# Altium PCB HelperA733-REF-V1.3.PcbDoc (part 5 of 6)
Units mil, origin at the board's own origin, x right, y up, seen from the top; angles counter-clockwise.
Board outline 5905.51 x 4133.86 mil, 2 copper layers (Top, Bottom), stack 12.7 mil thick; 446 components, 341 nets, 1706 pads, 1667 vias.
Unrouted connection lines stored in the file: 1382.
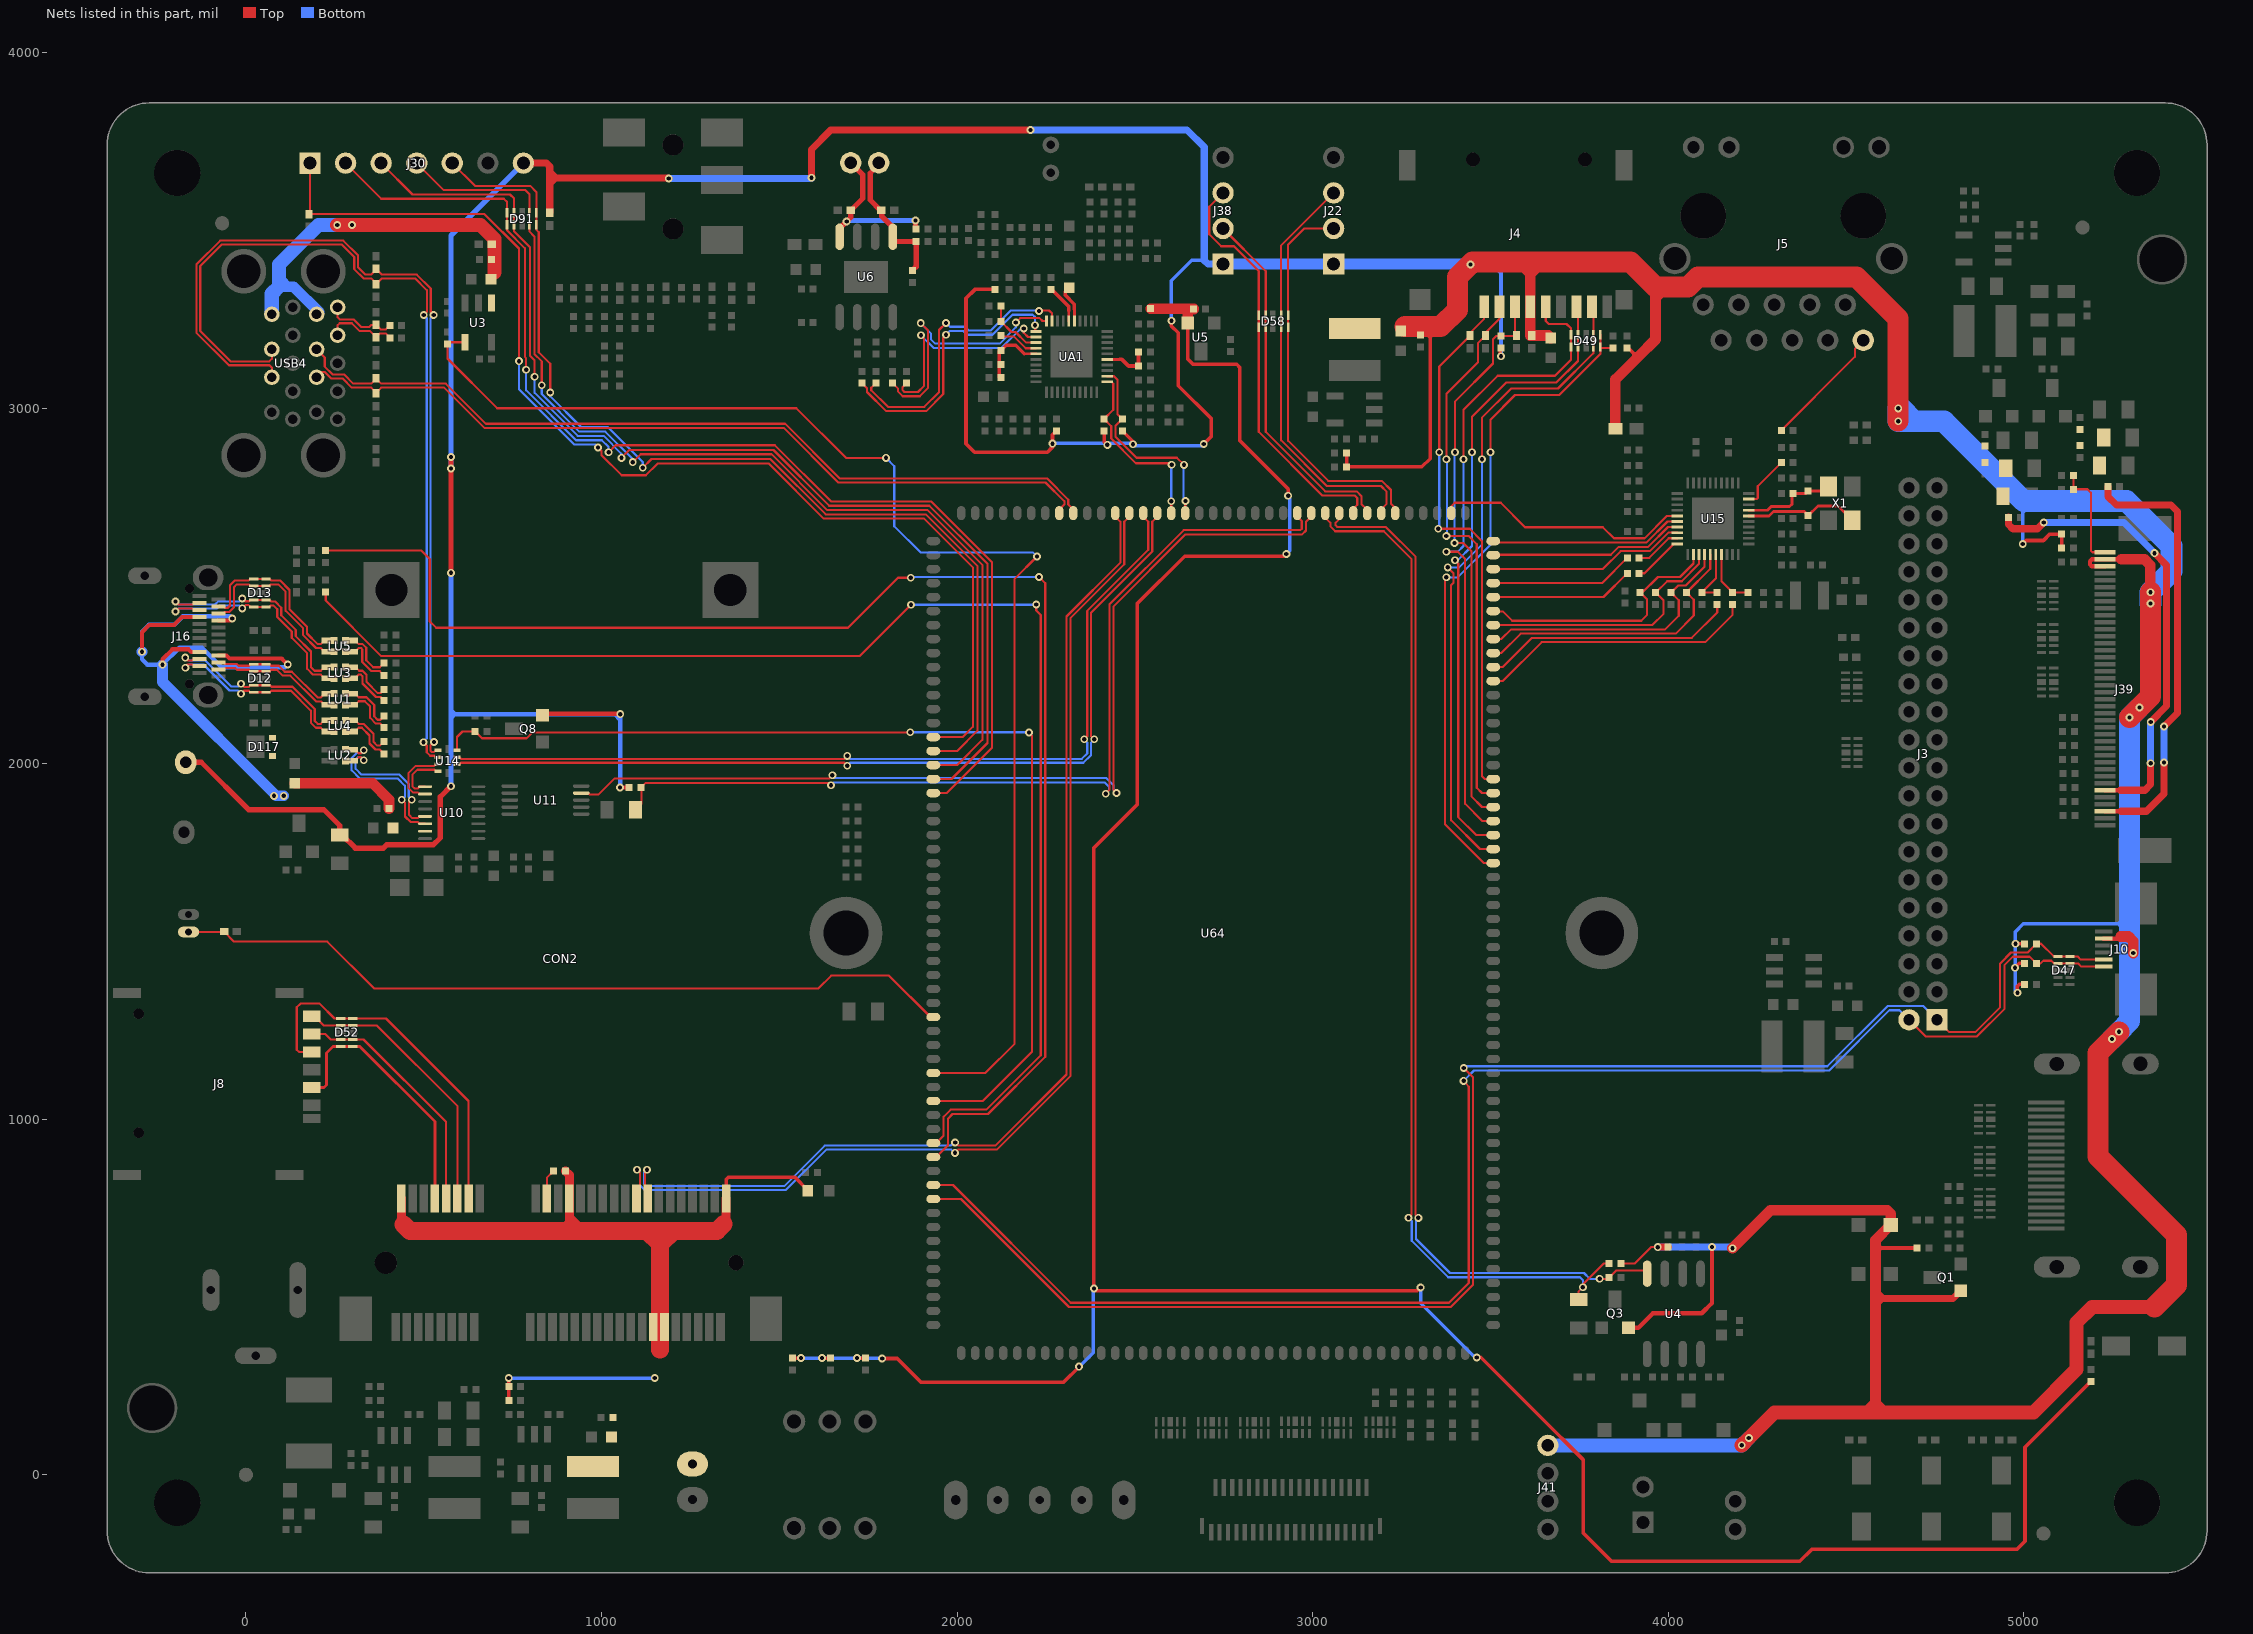
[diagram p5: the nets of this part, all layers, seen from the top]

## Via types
v1: diameter 22, hole 12, Top to Bottom, 1667 vias

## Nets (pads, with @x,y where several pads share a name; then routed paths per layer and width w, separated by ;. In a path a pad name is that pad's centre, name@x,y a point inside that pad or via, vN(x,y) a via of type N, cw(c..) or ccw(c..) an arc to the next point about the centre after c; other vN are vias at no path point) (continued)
RGMII0-RXCK: RE9.1 U64.84 | length 779.7
  Top w6: U64.84@3507.87,2232.28 3534.83,2232.28 3644.31,2341.76 4104.32,2341.76 4181.1,2418.54 RE9.1@4181.1,2447.84
RGMII0-RXCTL: RE14.1 U64.85 | length 716.3
  Top w6: U64.85@3507.87,2271.65 3534.92,2271.65 3617.03,2353.76 4066.53,2353.76 4137.8,2425.03 RE14.1@4137.8,2447.84
RGMII0-RXD0: RE40.1 U15.25 U64.86 | length 815.7
  Top w6: U64.86@3507.87,2311.02 3530.39,2311.02 3585.13,2365.76 4020.9,2365.76 4071.64,2416.5 4071.64,2460.84 RE40.1@4051.18,2481.3 4118.11,2548.23 U15.25@4118.11,2588.58
RGMII0-RXD1: RE38.1 U15.24 U64.87 | length 782.1
  Top w6: U64.87@3507.87,2350.39 3530.85,2350.39 3558.22,2377.76 3991.37,2377.76 4029.47,2415.86 4029.47,2459.7 RE38.1@4007.87,2481.3 4027.71,2501.13 4049.16,2501.13 4102.36,2554.34 U15.24@4102.36,2588.58
RGMII0-RXD2: RE36.1 U15.23 U64.88 | length 743.1
  Top w6: U64.88@3507.87,2389.76 3954.88,2389.76 3986.9,2421.79 3986.9,2458.97 RE36.1@3964.57,2481.3 3996.92,2513.13 4038.02,2513.13 4086.61,2561.73 U15.23@4086.61,2588.58
RGMII0-RXD3: RE25.1 U15.22 U64.89 | length 731
  Top w6: U64.89@3507.87,2429.13 3509.51,2427.5 3535.63,2427.5 3561.36,2401.77 3923.94,2401.77 3940.76,2418.59 3940.76,2461.8 RE25.1@3921.26,2481.3 3927.3,2481.3 3971.14,2525.14 4033.06,2525.14 4070.87,2562.95 U15.22@4070.87,2588.58
RGMII0-TXCK: RE7.1 U64.90 | length 404.7
  Top w6: U64.90@3507.87,2468.5 3817.91,2468.5 RE7.1@3884.84,2535.43
RGMII0-TXCTL: RE5.1 U64.91 | length 406.3
  Top w6: U64.91@3507.87,2507.87 3813.97,2507.87 RE5.1@3884.84,2578.74
RGMII0-TXD0: U15.18 U64.92 | length 560.1
  Top w6: U64.92@3507.87,2547.24 3815.85,2547.24 3866.21,2597.6 3948.39,2597.6 4000.39,2649.61 U15.18@4025.59,2649.61
RGMII0-TXD1: U15.17 U64.93 | length 550.3
  Top w6: U64.93@3507.87,2586.61 3508.69,2587.43 3838.65,2587.43 3860.89,2609.67 3943.49,2609.67 3999.17,2665.35 U15.17@4025.59,2665.35
RGMII0-TXD2: U15.16 U64.94 | length 544.1
  Top w6: U64.94@3507.87,2625.99 3512.18,2621.67 3938.51,2621.67 3997.95,2681.1 U15.16@4025.59,2681.1
RGMII0-TXD3: U15.15 U64.96 | length 726.3
  Top w6: U64.96@3389.76,2704.73 3389.76,2723.61 3399.75,2733.6 3528.8,2733.6 3597.37,2665.02 3816.12,2665.02 3847.33,2633.82 3933.69,2633.82 3996.72,2696.85 U15.15@4025.59,2696.85
RSET: RE22.2 U15.39 | length 153.1
  Top w6: U15.39@4226.38,2744.09 4248.32,2744.09 4251.79,2747.56 4251.79,2780.33 RE22.2@4317.91,2846.46
RTC-IN: D174.2 J14.2 U64.166 | length 2224.6
  Top w6: J14.2@-161.42,1526.57 -62.29,1526.57 D174.2@-61.31,1527.56 -61.31,1526.94 -33.75,1499.38 228.9,1499.38 360.31,1367.97 1610.22,1367.97 1646.25,1404 1808.6,1404 1925.19,1287.4 U64.166@1933.07,1287.4
RX-1N: D13.5 D13.6 J16.B10 LU3.4 RU119.1 | length 649.8
  Top w6: v1(-197.94,2427.93) -189.42,2436.44 -150.71,2436.44 -146.35,2432.09 J16.B10@-130.9,2432.09 ; v1(-10.42,2436.78) -1.3,2445.91 7.7,2445.91 12.66,2440.94 D13.5@22.33,2440.94 66.35,2440.94 70.69,2445.29 76.99,2445.29 88.21,2434.07 88.21,2412.23 128.96,2371.48 128.96,2354.14 172.2,2310.9 172.2,2266.66 188.46,2250.41 210.23,2250.41 220.47,2240.17 LU3.4@227.36,2240.17
  Bottom w6: v1(-197.94,2427.93) -189.44,2436.43 -82.42,2436.43 -73.57,2445.29 -18.92,2445.29 v1(-10.42,2436.78)
RX-1P: D13.4 D13.7 J16.B11 LU3.3 RU116.1 | length 648.8
  Top w6: v1(-197.94,2455.93) -189.46,2447.45 -149.89,2447.45 -145.58,2451.77 J16.B11@-130.9,2451.77 ; v1(-10.42,2464.78) -2.55,2456.92 8.84,2456.92 12.55,2460.62 D13.4@22.33,2460.62 66.14,2460.62 70.48,2456.28 81.62,2456.28 99.29,2438.62 99.29,2417.02 140.12,2376.18 140.12,2358.54 183.2,2315.46 183.2,2271.21 193.01,2261.41 210.23,2261.41 220.47,2271.65 LU3.3@227.36,2271.65
  Bottom w6: v1(-197.94,2455.93) -189.44,2447.43 -86.98,2447.43 -78.12,2456.28 -18.92,2456.28 v1(-10.42,2464.78)
RX-2N: D12.1 D12.10 J16.A10 LU1.3 RU109.1 | length 353.8
  Top w6: J16.A10@-77.76,2284.45 -62.41,2284.45 -58.07,2280.11 -25.77,2280.11 -20.85,2275.18 8.97,2275.18 13.32,2279.53 D12.1@22.33,2279.53 66.61,2279.53 70.96,2275.18 92.27,2275.18 108.93,2258.52 129.29,2258.52 201.55,2186.27 210.19,2186.27 220.77,2196.84 LU1.3@227.36,2196.84
RX-2P: D12.2 D12.9 J16.A11 LU1.4 RU108.1 | length 353.5
  Top w6: J16.A11@-77.76,2264.77 -62.98,2264.77 -58.64,2269.11 -30.33,2269.11 -25.4,2264.18 8.05,2264.18 12.4,2259.84 D12.2@22.33,2259.84 66.96,2259.84 71.3,2264.18 86.87,2264.18 103.56,2247.49 124.77,2247.49 197.11,2175.15 211.16,2175.15 220.94,2165.36 LU1.4@227.36,2165.36
RXC/PHYAD1: RE9.2 RE23.2 U15.27 | length 163.6
  Top w6: U15.27@4149.61,2588.58 4149.61,2512.8 RE9.2@4181.1,2481.3 RE23.2@4224.41,2481.3
RXCTL/PHYAD2: RE14.2 RE34.2 U15.26 | length 166.9
  Top w6: U15.26@4133.86,2588.58 4133.86,2520.67 RE34.2@4094.49,2481.3 4095.01,2481.3 RE14.2@4137.8,2481.3
S-TWI0-CTP0-SCK: D47.2 D47.9 J3.2 J10.6 R214.1 U64.178 | length 4335.5
  Top w6: U64.178@1933.07,814.96 1988.5,814.96 2319.55,483.91 3383.4,483.91 3438.91,539.42 3438.91,1091.93 v1(3424.58,1107.93) ; J3.2@4677.17,1279.53 4723.72,1232.97 4868.44,1232.97 4945.25,1309.78 4945.25,1433.21 4969.14,1457.09 5016.37,1457.09 R214.1@5035.21,1438.25 5047.28,1438.25 5054.92,1445.89 5077.44,1445.89 5085.08,1438.25 D47.2@5095.93,1438.25 5152.23,1438.25 5161.35,1429.13 J10.6@5224.41,1429.13
  Bottom w6: v1(3424.58,1107.93) 3453.84,1137.19 4452.59,1137.19 4621.86,1306.46 4650.23,1306.46 J3.2@4677.17,1279.53
S-TWI0-CTP0-SDA: D47.1 D47.10 J3.1 J10.5 R7.1 U64.179 | length 4385.8
  Top w6: U64.179@1933.07,775.59 2010.87,775.59 2314.56,471.9 3388.56,471.9 3450.91,534.25 3450.91,1117.94 v1(3424.92,1143.93) ; J3.1@4755.91,1279.53 4790.42,1245.01 4863.51,1245.01 4933.25,1314.75 4933.25,1438.18 4964.17,1469.09 5010.93,1469.09 R7.1@5035.21,1493.37 5048.44,1493.37 5083.87,1457.94 D47.1@5095.93,1457.94 5151.15,1457.94 5160.27,1448.82 J10.5@5224.41,1448.82
  Bottom w6: v1(3424.92,1143.93) 3430.18,1149.19 4447.6,1149.19 4616.94,1318.53 4650.48,1318.53 4716.91,1318.53 J3.1@4755.91,1279.53
SBU1-DC: RU23.1 U64.175 | length 3855.9
  Top w6: RU23.1@224.41,2483.27 224.41,2458.73 380.83,2302.31 1725.74,2302.31 v1(1870.37,2446.94) ; U64.175@1933.07,933.07 1940.94,933.07 1962.27,954.4 1962.27,1006.96 1982.23,1026.92 2082.35,1026.92 2235.31,1179.88 2235.31,2418.26 2222.81,2430.76 v1(2222.81,2447.32)
  Bottom w6: v1(1870.37,2446.94) 2222.81,2446.94 v1(2222.81,2447.32)
SBU2-DC: RU24.1 U64.176 | length 4090.2
  Top w6: RU24.1@224.41,2599.41 493.06,2599.41 516.91,2575.56 516.91,2400 534.8,2382.11 1693.35,2382.11 1833.97,2522.73 v1(1869.77,2522.73) ; U64.176@1933.07,893.7 1940.94,893.7 1974.27,927.03 1974.27,1001.83 1986.96,1014.52 2086.92,1014.52 2248.04,1175.64 2248.04,2507.46 v1(2230.62,2524.88)
  Bottom w6: v1(1869.77,2522.73) 1871.91,2524.88 v1(2230.62,2524.88)
SDC0-CLK: D49.1 D49.10 J4.5 U64.74 | length 1855.6
  Top w6: v1(3376,2596) 3408.29,2596 3428.9,2575.39 3428.9,1886.95 3477.27,1838.58 U64.74@3507.87,1838.58 ; v1(3424,2856) 3424,2994.85 3520.16,3091.01 3681.56,3091.01 3726.38,3135.83 3726.38,3224.07 3713.9,3236.55 3663.84,3236.55 3655.41,3244.98 3655.41,3285.43 J4.5@3655.51,3285.43
  Bottom w6: v1(3376,2596) 3408,2596 3424,2612 v1(3424,2856)
SDC0-CMD: D126.2 J4.3 R11.2 U64.75 | length 1606.6
  Top w6: v1(3399.14,2620.47) 3423.96,2620.47 3446.46,2597.98 3446.46,1907.87 3476.38,1877.95 U64.75@3507.87,1877.95 ; v1(3400,2876) 3400,3018.09 3507.24,3125.33 3507.24,3193.61 3516.45,3202.82 R11.2@3529.64,3202.82 D126.2@3568.9,3202.82 ; J4.3@3568.9,3285.43 D126.2@3568.9,3202.82 ; D126.2@3568.9,3202.82 3568.9,3197.13 D126.2@3572.95,3204.09 3571.68,3202.82 D126.2@3568.9,3202.82
  Bottom w6: v1(3399.14,2620.47) 3399.14,2876.86 v1(3400,2876)
SDC0-D0: D49.2 D49.9 J4.7 U64.73 | length 1791.5
  Top w6: v1(3400,2572) 3409.48,2562.52 3409.48,1849.73 3460,1799.21 U64.73@3507.87,1799.21 ; v1(3448,2876) 3448,2976 3544,3072 3685.46,3072 3746.06,3132.6 D49.2@3746.06,3171.85 D49.9@3746.06,3206.3 3746.06,3268.03 3742.13,3271.97 J4.7@3742.13,3285.43
  Bottom w6: v1(3400,2572) 3408,2572 3448,2612 v1(3448,2876)
SDC0-D1: D49.4 D49.7 J4.8 U64.72 | length 1873
  Top w6: v1(3380,2552) 3396.06,2535.94 3396.06,2509.08 3389.54,2502.56 3389.54,1840.78 3470.47,1759.84 U64.72@3507.87,1759.84 ; v1(3476,2856) 3476,2972.63 3558.37,3054.99 3690.1,3054.99 3789.37,3154.26 D49.4@3789.37,3171.85 D49.7@3789.37,3206.3 3789.37,3258.79 3785.43,3262.72 J4.8@3785.43,3285.43
  Bottom w6: v1(3380,2552) 3412,2552 3476,2616 v1(3476,2856)
SDC0-D2: D128.2 J4.1 U64.77 | length 1516.6
  Top w6: v1(3353.2,2660.88) v1@3352.4,2660.6 ; v1(3356,2876) 3356,3117.06 D128.2@3443.03,3204.09 3443.03,3211.68 3482.28,3250.94 J4.1@3482.28,3285.43 ; U64.77@3507.87,1956.69 3484.25,1956.69 3476.38,1964.57 3476.38,2625.88 3441.65,2660.6 v1@3352.4,2660.6 ; v1@3352.4,2660.6 3351.67,2660.6 3351.75,2660.38 v1@3352.4,2660.6
  Bottom w6: v1(3353.2,2660.88) 3356,2660.88 v1(3356,2876)
SDC0-D3: D127.2 J4.2 U64.76 | length 1544.1
  Top w6: v1(3376,2640) 3377.89,2640.59 3438.09,2640.59 3461.41,2617.26 3461.41,1932.29 3476.38,1917.32 U64.76@3507.87,1917.32 ; v1(3376,2856) 3376.42,2856.53 3376.42,3040.04 3464.57,3128.19 3464.57,3182.32 D127.2@3486.34,3204.09 3484.25,3209.6 3525.59,3250.94 J4.2@3525.59,3285.43
  Bottom w6: v1(3376,2640) 3377.57,2640.6 3377.57,2855.38 3376.47,2856.47 v1(3376,2856)
SDC0-DET: D49.5 D49.6 R294.1 U64.71 | length 1867.1
  Top w6: v1(3376,2524) 3372.21,2520.21 3372.21,1829.33 3481.06,1720.47 U64.71@3507.87,1720.47 ; v1(3500,2876) 3500,2967.62 3569.13,3036.75 3693.86,3036.75 3809.06,3151.94 D49.5@3809.06,3171.85 ; D49.6@3809.06,3206.3 D49.5@3809.06,3171.85 ; R294.1@3844.6,3169.36 3811.55,3169.36 D49.5@3809.06,3171.85
  Bottom w6: v1(3376,2524) 3408,2524 3500,2616 v1(3500,2876)
SPI0-CLK: D91.1 D91.10 J30.2 U64.150 | length 3326.1
  Top w6: J30.2@280.31,3688.98 380.43,3588.86 725.39,3588.86 734.07,3580.18 D91.10@734.07,3549.44 D91.1@734.07,3514.99 734.07,3499.76 784.36,3449.47 784.36,3144.19 788,3140.55 v1(788,3108) ; v1(1020,2876) 1039.54,2895.54 1487.45,2895.54 1645.42,2737.57 1926.73,2737.57 2098.21,2566.09 2098.21,2044.81 1970.72,1917.32 U64.150@1933.07,1917.32
  Bottom w6: v1(788,3108) 788,3049.77 928.23,2909.55 1001.12,2909.55 1020,2890.67 v1(1020,2876)
SPI0-CS0: D91.5 D91.6 J30.5 U64.147 | length 2900.9
  Top w6: J30.5@580.31,3688.98 644.43,3624.86 799.56,3624.86 816.75,3607.67 D91.6@816.75,3549.44 D91.5@816.75,3514.99 816.75,3501.13 823.51,3494.37 823.51,3157.07 856,3124.58 v1(856,3044) ; v1(1116,2832) 1140.59,2856.59 1474.71,2856.59 1630.26,2701.04 1912.29,2701.04 2057,2556.33 2057,2092.44 2000,2035.43 U64.147@1933.07,2035.43
  Bottom w6: v1(856,3044) 856,3032.99 942.37,2946.62 1017.85,2946.62 1116,2848.47 v1(1116,2832)
SPI0-CS1: D88.1 J30.1 U64.146 | length 3261.4
  Top w6: J30.1@180.31,3688.98 180.31,3548.71 D88.1@177.17,3545.56 671.09,3545.56 768,3448.65 v1(768,3132) ; v1(989.95,2889.46) 1000,2879.41 1000,2867.72 1056.69,2811.02 1124.48,2811.02 1157.71,2844.25 1470.05,2844.25 1625.32,2688.98 1907.38,2688.98 2044.28,2552.07 2044.28,2103.34 2015.75,2074.8 U64.146@1933.07,2074.8
  Bottom w6: v1(768,3132) 768,3052.8 923.27,2897.54 981.87,2897.54 v1(989.95,2889.46)
SPI0-MISO: D91.4 D91.7 J30.4 U64.148 | length 3050.7
  Top w6: J30.4@480.31,3688.98 556.43,3612.86 786.36,3612.86 797.06,3602.16 D91.7@797.06,3549.44 D91.4@797.06,3514.99 797.06,3496.85 811.16,3482.75 811.16,3152.19 832,3131.35 v1(832,3064) ; v1(1088,2848) 1110.02,2870.02 1478.37,2870.02 1635.29,2713.1 1917.2,2713.1 2071.19,2559.11 2071.19,2067.26 2000,1996.06 U64.148@1933.07,1996.06
  Bottom w6: v1(832,3064) 832,3039.72 937.87,2933.85 1010.87,2933.85 1088,2856.72 v1(1088,2848)
SPI0-MOSI: D91.2 D91.9 J30.3 U64.149 | length 3181.8
  Top w6: J30.3@380.31,3688.98 468.43,3600.86 742.76,3600.86 753.75,3589.87 D91.9@753.75,3549.44 D91.2@753.75,3514.99 753.75,3497.09 798.73,3452.12 798.73,3146.94 812,3133.66 v1(812,3088) ; v1(1056,2860) 1078.02,2882.02 1483.67,2882.02 1640.35,2725.34 1921.93,2725.34 2085.54,2561.73 2085.54,2057.98 1984.25,1956.69 U64.149@1933.07,1956.69
  Bottom w6: v1(812,3088) 812,3042.75 932.99,2921.76 1005.89,2921.76 1056,2871.64 v1(1056,2860)
SPKR+: CA85.1 D118.2 J37.1 U6.8 | length 472.7
  Top w15: U6.8@1669.4,3481.79 U6.8@1669.4,3504.77 ; U6.8@1669.4,3506.79 U6.8@1669.4,3504.77 ; J37.1@1700.81,3689.85 1734.85,3655.82 1734.85,3590.07 D118.2@1701.02,3556.24 1701.02,3536.39 v1(1689.43,3524.79) U6.8@1669.4,3504.77 ; v1(1882.88,3527.6) 1882.88,3503.36 1884.84,3503.36 CA85.1@1884.84,3503.94
  Bottom w15: v1(1689.43,3524.79) 1692.24,3527.6 v1(1882.88,3527.6)
SPKR-: CA88.1 D20.2 J37.2 R181.2 U6.5 | length 413.5
  Top w15: J37.2@1779.55,3689.85 1782.37,3687.04 1755.85,3660.52 1755.85,3585.46 1785.07,3556.24 D20.2@1787.07,3556.24 1788.57,3556.24 1788.57,3538.73 1819.4,3507.89 U6.5@1819.4,3481.79 1819.4,3468.5 CA88.1@1884.84,3468.5 1884.84,3397.64 R181.2@1874.02,3386.81
SPOLN: R192.1 UA1.12 | length 617.1
  Top w6: R192.1@1858.27,3069.88 1846.19,3057.8 1846.19,3051.33 1852.1,3045.42 1890.16,3045.42 1906.61,3061.87 1906.61,3196.45 v1(1898.24,3204.82) ; v1(2187.48,3223.68) 2187.48,3211.99 2199.64,3199.83 UA1.12@2221.65,3199.83
  Bottom w6: v1(1898.24,3204.82) 1933.87,3169.19 2124.74,3169.19 2176.18,3220.63 2184.43,3220.63 v1(2187.48,3223.68)
SPOLP: R193.1 UA1.11 | length 789.9
  Top w6: R193.1@1732.28,3069.88 1746.72,3055.45 1746.72,3045.3 1800.71,2991.31 1912.89,2991.31 1961,3039.42 1961,3198.3 v1(1969,3206.3) ; v1(2218.93,3233.06) 2219.97,3233.02 2219.97,3215.58 UA1.11@2221.65,3215.58
  Bottom w6: v1(1969,3206.3) 1979.34,3216.64 2017.29,3216.64 2027.63,3206.3 2099.69,3206.3 2155.93,3262.54 2212.39,3262.54 2218.93,3256 v1(2218.93,3233.06) v1@2213.97,3233.02
SPORN: R194.1 UA1.10 | length 748.7
  Top w6: R194.1@1818.9,3069.88 1834.16,3054.62 1834.16,3046.28 1847.15,3033.29 1895,3033.29 1918.62,3056.91 1918.62,3217.98 v1(1897.66,3238.94) ; v1(2165.36,3240.85) 2177.57,3253.06 2232.25,3253.06 2240.21,3245.1 UA1.10@2251.18,3245.1
  Bottom w6: v1(1897.66,3238.94) 1926.42,3210.18 1926.42,3193.61 1938.84,3181.19 2119.69,3181.19 2165.36,3226.86 v1(2165.36,3240.85)
SPORP: R191.1 UA1.9 | length 811.1
  Top w6: R191.1@1771.65,3069.88 1758.77,3057 1758.77,3050.33 1805.79,3003.31 1907.65,3003.31 1948.99,3044.65 1948.99,3219.42 v1(1969.11,3239.54) ; v1(2230.13,3273.12) 2230.13,3274.56 2258.59,3274.56 2266.92,3266.23 UA1.9@2266.92,3245.1
  Bottom w6: v1(1969.11,3239.54) 1979.97,3228.68 2022.34,3228.68 2032.72,3218.3 2094.72,3218.3 2150.98,3274.56 2225.48,3274.56 v1(2230.13,3273.12)
TRM-CTR: C81.2 J5.1 | length 349.3
  Top w6: C81.2@4317.91,2937.01 4411.96,3031.05 4411.96,3031.46 4524.95,3144.45 4524.95,3167.06 J5.1@4548.61,3190.72
TWI8-SCK: RA27.1 U64.115 UA1.32 | length 572.3
  Top w6: UA1.32@2422.44,3089.59 2441.18,3089.59 2451.25,3079.53 2451.25,2982.81 RA27.1@2464.57,2969.49 2445.72,2950.64 2445.72,2919.33 2504.57,2860.48 2618.26,2860.48 v1(2638.4,2840.33) ; U64.115@2641.73,2704.73 2641.73,2738.37 v1(2642.21,2738.86)
  Bottom w6: v1(2638.4,2840.33) 2636.29,2840.33 2636.29,2744.78 v1(2642.21,2738.86)
TWI8-SDA: RA28.1 U64.116 UA1.31 | length 529.1
  Top w6: UA1.31@2422.44,3073.84 2434.25,3073.84 2439.21,3068.88 2439.21,2995.31 RA28.1@2413.39,2969.49 2433.72,2949.15 2433.72,2914.25 2502.95,2845.02 2598.9,2845.02 v1(2603.45,2840.47) ; v1(2602.31,2738.17) 2602.36,2738.11 U64.116@2602.36,2704.73
  Bottom w6: v1(2602.31,2738.17) 2602.31,2839.32 v1(2603.45,2840.47)
TX-1N: D13.2 D13.9 J16.A3 LU5.4 RU112.1 | length 497.2
  Top w6: J16.A3@-77.76,2422.24 -63.2,2422.24 -58.86,2426.58 -47.14,2426.58 -33.7,2440.02 -33.7,2496.52 -25.88,2504.34 7.41,2504.34 11.76,2500 D13.2@22.33,2500 65.66,2500 70,2504.34 91.15,2504.34 111.55,2483.94 111.55,2430.14 160.83,2380.86 160.83,2361.33 196.96,2325.21 210.23,2325.21 220.47,2314.97 LU5.4@227.36,2314.97
TX-1P: D13.1 D13.10 J16.A2 LU5.3 RU111.1 | length 497.3
  Top w6: J16.A2@-77.76,2441.93 -62.35,2441.93 -58,2437.58 -51.81,2437.58 -44.71,2444.68 -44.71,2501.31 -30.68,2515.34 7.73,2515.34 12.07,2519.68 D13.1@22.33,2519.68 66.61,2519.68 70.96,2515.34 95.71,2515.34 122.72,2488.33 122.72,2434.53 171.83,2385.42 171.83,2365.89 201.51,2336.21 210.23,2336.21 220.47,2346.45 LU5.3@227.36,2346.45
TX-2N: D12.4 D12.7 J16.B3 LU4.3 RU114.1 | length 555
  Top w6: v1(-170.8,2298.18) -162.85,2290.23 -162.85,2289.95 -151.02,2289.95 -146.68,2294.29 J16.B3@-130.9,2294.29 ; v1(-13.7,2224.77) -4.94,2216 7.81,2216 12.28,2220.47 D12.4@22.33,2220.47 67.5,2220.47 71.84,2216.13 131.17,2216.13 193.63,2153.67 193.63,2119.86 201.69,2111.8 210.23,2111.8 220.47,2122.04 LU4.3@227.36,2122.04
  Bottom w6: v1(-170.8,2298.18) -167.62,2298.18 -159.38,2289.95 -114.25,2289.95 -41.14,2216.84 -21.63,2216.84 v1(-13.7,2224.77)
TX-2P: D12.5 D12.6 J16.B2 LU4.4 RU113.1 | length 559.7
  Top w6: v1(-170.33,2269.88) -169.98,2270.65 -172.41,2271.75 -172.31,2271.86 -165.22,2278.95 -151.07,2278.95 -146.73,2274.61 J16.B2@-130.9,2274.61 ; v1(-13.7,2196.77) -5.47,2205 8.25,2205 12.46,2200.79 D12.5@22.33,2200.79 67.28,2200.79 71.62,2205.13 126.62,2205.13 182.63,2149.12 182.63,2114.91 196.74,2100.8 210.23,2100.8 220.47,2090.56 LU4.4@227.36,2090.56
  Bottom w6: v1(-170.33,2269.88) -168.3,2269.89 -159.25,2278.95 -119.22,2278.95 -46.09,2205.82 -22.76,2205.82 v1(-13.7,2196.77)
TXC: RE7.2 U15.20 | length 141.5
  Top w6: RE7.2@3918.31,2535.43 3933.39,2535.43 4016.07,2618.11 U15.20@4025.59,2618.11
TXCTL: RE5.2 U15.19 | length 130.1
  Top w6: RE5.2@3918.31,2578.74 3946.5,2578.74 4001.61,2633.86 U15.19@4025.59,2633.86
TYPEC-RX1N: LU3.1 R76.2 RU119.2 | length 154.9
  Top w6: RU119.2@280.51,2240.16 LU3.1@300.19,2240.17 ; LU3.1@300.19,2240.17 306.39,2240.17 316.63,2250.41 323.37,2250.41 327.91,2245.87 327.91,2225.38 365.87,2187.41 378.53,2187.41 R76.2@388.78,2177.17
TYPEC-RX1P: LU3.2 R77.2 RU116.2 | length 154.8
  Top w6: RU116.2@280.51,2271.65 LU3.2@300.19,2271.65 308.55,2271.65 318.79,2261.41 327.93,2261.41 338.98,2250.35 338.98,2229.93 370.49,2198.41 378.53,2198.41 R77.2@388.78,2208.66
TYPEC-RX2N: LU1.2 R65.2 RU109.2 | length 161.6
  Top w6: RU109.2@280.51,2196.85 LU1.2@300.19,2196.84 307.08,2196.84 317.32,2186.6 339.1,2186.6 360.74,2164.97 360.74,2132.97 370.1,2123.61 378.53,2123.61 R65.2@388.78,2133.86
TYPEC-RX2P: LU1.1 R69.2 RU108.2 | length 161.6
  Top w6: RU108.2@280.51,2165.35 LU1.1@300.19,2165.36 307.08,2165.36 317.32,2175.6 334.55,2175.6 349.43,2160.71 349.43,2128.65 365.47,2112.61 378.53,2112.61 R69.2@388.78,2102.36
TYPEC-TX1N: C139.2 LU5.1 RU112.2 | length 165.2
  Top w6: RU112.2@280.51,2314.96 LU5.1@300.19,2314.97 ; LU5.1@300.19,2314.97 307.08,2314.97 317.32,2325.21 323.48,2325.21 327.27,2321.42 327.27,2286.09 353.11,2260.25 376.56,2260.25 C139.2@388.78,2248.03
TYPEC-TX1P: C140.2 LU5.2 RU111.2 | length 165.2
  Top w6: RU111.2@280.51,2346.46 LU5.2@300.19,2346.45 307.08,2346.45 317.32,2336.21 328.08,2336.21 338.27,2326.02 338.27,2290.68 357.71,2271.25 376.56,2271.25 C140.2@388.78,2283.46
TYPEC-TX2N: C141.2 LU4.2 RU114.2 | length 156.1
  Top w6: RU114.2@280.51,2122.05 LU4.2@300.19,2122.04 307.08,2122.04 317.32,2111.8 330.77,2111.8 358.56,2084.02 358.56,2061.38 369.16,2050.78 376.56,2050.78 C141.2@388.78,2062.99
TYPEC-TX2P: C142.2 LU4.1 RU113.2 | length 156
  Top w6: RU113.2@280.51,2090.55 LU4.1@300.19,2090.56 307.08,2090.56 317.32,2100.8 325.95,2100.8 347.55,2079.2 347.55,2056.79 364.57,2039.78 376.56,2039.78 C142.2@388.78,2027.56
U3-TXN: C213.2 D74.1 USB4.17 | length 205.8
  Top w6: USB4.17@257.87,3204.72 257.87,3233.09 263.37,3238.59 297.83,3238.59 319.16,3217.26 348.4,3217.26 366.26,3199.4 D74.1@366.26,3199.26 377.21,3210.21 393.41,3210.21 405.63,3197.99 C213.2@404.65,3197.01
U3-TXP: C214.2 D75.1 USB4.18 | length 198.7
  Top w6: USB4.18@257.87,3283.46 257.87,3255.09 263.37,3249.59 302.38,3249.59 323.72,3228.26 347.39,3228.26 353.26,3234.13 D75.1@366.26,3234.13 379.16,3221.23 393.43,3221.23 C214.2@404.65,3232.44
UART0-RX: D173.1 R291.1 U64.107 | length 2645
  Top w6: D173.1@1095.12,1870.08 1112.48,1887.44 1112.48,1931.81 R291.1@1111.22,1933.07 1124.03,1945.88 1642.24,1945.88 1647.16,1940.96 v1(1645.46,1939.27) ; v1(2417.9,1915.6) 2428.13,1925.83 2428.13,2447.47 2637.49,2656.83 2965.45,2656.83 2969.4,2660.77 2969.4,2682.35 2956.69,2695.06 U64.107@2956.69,2704.73
  Bottom w6: v1(1645.46,1939.27) 1653.34,1947.15 2415.02,1947.15 2427.68,1934.49 2427.68,1925.38 v1(2417.9,1915.6)
UART0-TX: U11.9 U64.106 | length 2774.1
  Top w6: U11.9@942.91,1917.32 962.23,1917.32 966.02,1913.53 991.8,1913.53 1037.02,1958.74 1640.68,1958.74 v1(1649.29,1967.35) ; v1(2448.54,1917.48) 2440.13,1925.89 2440.13,2442.49 2642.46,2644.83 2970.42,2644.83 2981.4,2655.8 2981.4,2680.61 2996.06,2695.27 U64.106@2996.06,2704.73
  Bottom w6: v1(1649.29,1967.35) 1647.73,1965.79 1654.38,1959.15 2419.99,1959.15 2439.68,1939.46 2439.68,1926.34 v1(2448.54,1917.48)
UART2-RX: D54.1 R44.1 U64.105 | length 2926.8
  Top w6: U64.105@3035.43,2704.73 3035.43,2691.91 3049.73,2677.61 3049.73,2667.55 3063.65,2653.63 3199.9,2653.63 3277.46,2576.07 3277.46,731.12 v1(3269.26,722.92) ; D54.1@3748.03,492.76 3748.03,515.75 v1(3759.84,527.56) 3759.84,535.43 3818.9,594.49 R44.1@3833.66,594.49
  Bottom w6: v1(3269.26,722.92) 3278.68,713.49 3278.68,658.22 3381.34,555.56 3751.97,555.56 3759.84,547.69 v1(3759.84,527.56)
UART2-TX: R47.2 U4.4 U64.104 | length 2937.1
  Top w6: U64.104@3074.8,2704.73 3074.8,2687.6 3064.58,2677.38 3064.58,2670.04 3068.98,2665.64 3205.37,2665.64 3289.52,2581.49 3289.52,730.24 3297.17,722.59 v1(3297.27,722.59) ; v1(3807.09,551.18) 3833.66,551.18 R47.2@3833.66,555.12 3853.35,574.8 3931.7,574.8 U4.4@3940.75,565.76
  Bottom w6: v1(3297.27,722.59) 3290.72,716.05 3290.72,663.19 3386.34,567.57 3763.14,567.57 3779.53,551.18 v1(3807.09,551.18)
UART3-RX: D58.2 D58.9 J22.3 U64.101 | length 1179.9
  Top w6: J22.3@3059.06,3605.12 2911.42,3457.48 D58.2@2911.42,3261.22 D58.9@2911.42,3226.77 2911.42,2909.45 3039.98,2780.89 3192.07,2780.89 3208.14,2764.82 3208.14,2730.91 3192.91,2715.68 U64.101@3192.91,2704.73
UART3-TX: D58.1 D58.10 J22.2 U64.100 | length 1115.2
  Top w6: J22.2@3059.06,3505.12 2976.04,3505.12 2931.1,3460.18 D58.1@2931.1,3261.22 D58.10@2931.1,3226.77 2931.1,2907.95 3043.78,2795.28 3194.65,2795.28 3220.18,2769.74 3220.18,2731.02 3232.28,2718.93 U64.100@3232.28,2704.73
UART4-RX: D58.5 D58.6 J38.3 U64.103 | length 1168.1
  Top w6: J38.3@2748.03,3605.12 2709.03,3566.12 2709.03,3488.96 2742.88,3455.12 2778.62,3455.12 2848.42,3385.31 D58.5@2848.42,3261.22 D58.6@2848.42,3226.77 2848.42,2933.07 3027.83,2753.67 3118.89,2753.67 3125.56,2747 3125.56,2727.91 3114.17,2716.53 U64.103@3114.17,2704.73
UART4-TX: D58.4 D58.7 J38.2 U64.102 | length 1020.1
  Top w6: J38.2@2748.03,3505.12 2868.11,3385.04 D58.4@2868.11,3261.22 D58.7@2868.11,3226.77 2868.11,2933.07 3035.47,2765.71 3123.86,2765.71 3137.56,2752.01 3137.56,2729.83 3153.54,2713.85 U64.102@3153.54,2704.73
UPUSB-DM: LU2.3 RU22.1 U10.5 | length 427.1
  Top w6: RU22.1@280.51,2007.87 LU2.3@300.19,2007.88 307.08,2007.88 317.32,2018.12 322.9,2018.12 v1(331.4,2009.62) ; v1(466.4,1898.32) 465.37,1898.32 458.42,1891.37 458.42,1856.02 467.6,1846.84 483.2,1846.84 488.13,1851.77 U10.5@503.94,1851.77
  Bottom w6: v1(331.4,2009.62) 322.07,2018.96 315.87,2018.96 308.46,2011.55 308.46,1985.61 324.63,1969.44 431.06,1969.44 457.9,1942.6 457.9,1906.82 v1(466.4,1898.32)
UPUSB-DP: LU2.4 RU19.1 U10.6 | length 463.4
  Top w6: RU19.1@280.51,2039.37 LU2.4@300.19,2039.36 ; LU2.4@300.19,2039.36 307.08,2039.36 317.32,2029.12 322.9,2029.12 v1(331.4,2037.62) ; v1(438.4,1898.32) 439.43,1898.32 447.42,1890.34 447.42,1851.46 463.04,1835.84 483.12,1835.84 488.05,1830.91 U10.6@503.94,1830.91
  Bottom w6: v1(331.4,2037.62) 323.86,2030.08 311.42,2030.08 297.31,2015.97 297.31,1981.2 320.07,1958.44 426.5,1958.44 446.9,1938.04 446.9,1906.82 v1(438.4,1898.32)
USB0-DM: U14.7 U64.117 | length 2566
  Top w6: U14.7@593.51,1998.03 600.58,1998.03 604.92,2002.37 1682.57,2002.37 v1(1691.07,1993.87) ; v1(2385.51,2068.47) 2377.01,2076.97 2377.01,2167.42 2377.01,2424.96 2548.8,2596.75 2548.8,2680.69 2562.99,2694.88 U64.117@2562.99,2704.73
  Bottom w6: v1(1691.07,1993.87) 1699.57,2002.37 2355.19,2002.37 2377.01,2024.19 2377.01,2059.97 v1(2385.51,2068.47)
USB0-DM-L0-: D171.1 U14.2 USB4.2 | length 2550.9
  Top w6: USB4.2@72.83,3165.35 72.83,3138.38 65.93,3131.48 -43.25,3131.48 -128.37,3216.61 -128.37,3399.44 -67.83,3459.98 269.37,3459.98 304.61,3424.74 304.61,3390.74 330.61,3364.74 352.39,3364.74 366.26,3350.87 D171.1@366.26,3348.87 381.72,3364.33 476,3364.33 508.74,3331.59 508.74,3270.32 v1(499.91,3261.49) ; v1(499.38,2059.97) 508.41,2050.94 508.41,2031.81 518.15,2022.06 529.56,2022.06 533.9,2017.71 U14.2@540.35,2017.71
  Bottom w6: v1(499.38,2059.97) 498.94,2061.73 508.41,2071.2 508.41,3252.99 v1(499.91,3261.49)
USB0-DM-L1-: U10.1 U14.4 | length 152.4
  Top w6: U10.1@503.94,1935.24 488.19,1935.24 483.26,1930.3 474.53,1930.3 467.99,1936.84 467.99,1968.56 482.12,1982.69 529.72,1982.69 534.07,1978.34 U14.4@540.35,1978.34
USB0-DP: U14.8 U64.118 | length 2547.8
  Top w6: U14.8@593.51,2017.71 600.33,2017.71 604.67,2013.37 1682.57,2013.37 v1(1691.07,2021.87) ; v1(2357.51,2068.47) 2366.01,2076.97 2366.01,2171.97 2366.01,2429.62 2537.8,2601.41 2537.8,2680.69 2523.62,2694.88 U64.118@2523.62,2704.73
  Bottom w6: v1(1691.07,2021.87) 1699.57,2013.37 2350.64,2013.37 2366.01,2028.75 2366.01,2059.97 v1(2357.51,2068.47)
USB0-DP-L0+: D170.1 U14.1 USB4.3 | length 2587.7
  Top w6: USB4.3@72.83,3086.61 72.83,3114.14 66.49,3120.48 -47.8,3120.48 -139.37,3212.05 -139.37,3404 -72.39,3470.98 273.93,3470.98 315.61,3429.3 315.61,3395.29 335.17,3375.74 352.39,3375.74 366.26,3389.61 D170.1@366.26,3391.61 382.53,3375.34 480.85,3375.34 519.75,3336.44 519.75,3269.64 v1(527.91,3261.49) ; v1(528.6,2060.78) 519.41,2051.59 519.41,2036.41 522.75,2033.06 529.2,2033.06 533.55,2037.4 U14.1@540.35,2037.4
  Bottom w6: v1(527.91,3261.49) 519.41,3252.99 519.41,2069.97 v1(528.6,2060.78)
USB0-DP-L1+: U10.2 U14.3 | length 189.5
  Top w6: U10.2@503.94,1914.37 488.19,1914.37 483.26,1919.3 469.35,1919.3 456.71,1931.94 456.71,1972.95 477.45,1993.69 529.37,1993.69 533.72,1998.03 U14.3@540.35,1998.03
USB0-SL-PL2: RU6.2 U14.9 U64.172 | length 2904.1
  Top w6: U14.9@593.51,2037.4 593.51,2075.14 608.92,2090.55 RU6.2@644.69,2090.55 663.84,2071.4 789.37,2071.4 805.9,2087.93 1868.41,2087.93 v1(1868.41,2088.53) ; U64.172@1933.07,1051.18 2072.39,1051.18 2210.22,1189.01 2210.22,2079.09 v1(2202,2087.31)
  Bottom w6: v1(1868.41,2088.53) 1868.7,2088.25 2189.05,2088.25 v1(2202,2087.31)
USB1-DM: CON2.36 U64.119 | length 3143.3
  Top w6: CON2.36@1098.43,777.62 1098.43,804.43 1108,814 1108,850 v1(1100,858) ; v1(1993.81,905.48) 2002.95,914.62 2111.97,914.62 2318.62,1121.27 2318.62,2409.24 2470.06,2560.68 2470.06,2680.69 2484.25,2694.88 U64.119@2484.25,2704.73
  Bottom w6: v1(1100,858) 1108.5,849.5 1108.5,813.72 1121.41,800.81 1518.47,800.81 1632.28,914.62 1983.89,914.62 1993.03,905.48 v1(1993.81,905.48)
USB1-DP: CON2.38 U64.120 | length 3124.9
  Top w6: CON2.38@1129.92,777.62 1122,769.7 1122,852 v1(1128,858) v1@1130.38,856.82 ; v1@1129.92,855.92 v1@1130.37,856.79 ; v1(1994.52,934.81) 2003.71,925.62 2107.42,925.62 2307.62,1125.83 2307.62,2413.82 2459.06,2565.26 2459.06,2680.69 2444.88,2694.88 U64.120@2444.88,2704.73
  Bottom w6: v1(1128,858) 1119.5,849.5 1119.5,818.28 1125.97,811.81 1513.91,811.81 1627.72,925.62 1981.48,925.62 1990.67,934.81 v1(1994.52,934.81)
USB2-DM: D71.1 U64.123 USB4.11 | length 2361.2
  Top w6: USB4.11@198.81,3165.35 221.73,3142.43 221.73,3116.67 244.13,3094.27 276.46,3094.27 302.08,3068.65 352.39,3068.65 D71.1@366.26,3082.52 ; D71.1@366.26,3084.52 D71.1@366.26,3082.52 ; U64.123@2326.77,2704.73 2326.77,2714.56 2312.58,2728.75 2312.58,2742.6 2253.32,2801.86 1670.43,2801.86 1516.31,2955.98 674.65,2955.98 561.98,3068.65 380.13,3068.65 D71.1@366.26,3082.52
USB2-DP: D70.1 U64.124 USB4.12 | length 2312.1
  Top w6: USB4.12@198.81,3086.61 213.73,3101.53 221.31,3101.53 239.57,3083.27 271.9,3083.27 297.52,3057.65 352.39,3057.65 D70.1@366.26,3043.78 ; D70.1@366.26,3041.78 D70.1@366.26,3043.78 ; U64.124@2287.4,2704.73 2287.4,2714.56 2301.58,2728.75 2301.58,2737.89 2248.63,2790.84 1665.81,2790.84 1512.23,2944.42 670.56,2944.42 557.33,3057.65 380.13,3057.65 D70.1@366.26,3043.78
USIM_CLK: CON2.12 D52.4 D52.7 J8.3 | length 773.7
  Top w6: J8.3@185.04,1289.37 193.5,1289.37 219.09,1263.78 D52.7@266.42,1263.78 368.36,1263.78 594.49,1037.66 CON2.12@594.49,777.62
USIM_DATA: CON2.10 D52.2 D52.9 J8.7 | length 694.9
  Top w6: J8.7@185.04,1239.37 223.82,1239.37 238.77,1224.41 D52.9@266.42,1224.41 330.7,1224.41 562.99,992.12 CON2.10@562.99,777.62
USIM_RST: CON2.14 D52.5 D52.6 J8.2 | length 1038.2
  Top w6: J8.2@185.04,1189.37 149.18,1189.37 143,1195.55 143,1314.82 153.41,1325.23 207.33,1325.23 249.1,1283.46 D52.6@266.42,1283.46 393.7,1283.46 625.99,1051.18 CON2.14@625.99,777.62
USIM_VCC: CON2.8 D52.1 D52.10 J8.1 | length 750.3
  Top w8: J8.1@185.04,1089.37 219.45,1089.37 226.21,1096.13 226.21,1186.1 244.83,1204.72 D52.10@266.42,1204.72 320.2,1204.72 531.5,993.42 CON2.8@531.5,777.62
VBUS1: CU2.2 CU3.2 D67.2 U3.1 USB4.1 USB4.10 | length 1133.8
  Top w40: v1(256.83,3515.2) v1(298.51,3515.2) 659.42,3515.2 699.39,3475.24 699.39,3382.23
  Bottom w30: 93.02,3341.66 116.27,3341.66 ; 93.02,3359.25 98.68,3359.25 116.27,3341.66 ; USB4.10@198.81,3263.77 205.35,3270.31 134.01,3341.66 116.27,3341.66
  Bottom w40: USB4.1@72.83,3263.77 72.83,3321.48 93.02,3341.66 93.02,3359.25 93.02,3403.78 204.44,3515.2 v1(256.83,3515.2) v1(298.51,3515.2)
VBUS-EN-PL13: RU7.2 U3.4 U64.170 | length 3738.1
  Top w6: U3.4@616.14,3185.04 571.85,3185.04 RU7.2@566.93,3180.12 566.93,3139.29 706.59,2999.63 1548.03,2999.63 1687.66,2860 v1(1800,2860) ; U64.170@1933.07,1129.92 2079.02,1129.92 2161.82,1212.71 2161.82,2519.75 v1(2224.58,2582.51)
  Bottom w6: v1(1800,2860) 1823.46,2836.54 1823.46,2667.74 1897.12,2594.08 2213.01,2594.08 v1(2224.58,2582.51)
VBUS-USB: C179.1 C180.1 CU7.1 D117.1 D117.2 J16.A4 J16.A9 J16.B4 J16.B9 U10.7 | length 2260
  Top w12: v1(-292.51,2314.68) -292.51,2369.67 -272.24,2389.94 -201.93,2389.94 -179.48,2412.4 J16.B9@-130.9,2412.4 ; v1(-234.6,2278.47) -234.6,2293.85 -206.95,2321.5 -161.59,2321.5 -154.07,2313.98 J16.B4@-130.9,2313.98 ; J16.A9@-77.76,2304.14 -54.58,2304.14 -45.95,2295.51 100.5,2295.51 v1(117.47,2278.54) ; J16.A4@-77.76,2402.56 -44.48,2402.56 v1(-38.53,2408.51)
  Top w30: CU7.1@137.8,1944.49 356.93,1944.49 402.56,1898.86 C180.1@402.56,1874.02
  Bottom w12: v1(-292.51,2314.68) -292.51,2293.63 -277.35,2278.47 v1(-234.6,2278.47) -187.25,2325.82 -123.7,2325.82 -68.92,2271.04 109.97,2271.04 v1(117.47,2278.54) ; v1@-292.24,2314.95 -292.24,2371.5 -273.32,2390.42 -201.45,2390.42 -177.35,2414.52 -44.54,2414.52 v1(-38.53,2408.51)
  Bottom w30: v1(-292.51,2314.68) v1@-292.24,2314.95 ; v1(-234.6,2278.47) -234.6,2229.58 85.53,1909.45 v1(106.3,1909.45)
  other v1: 78.74,1909.45
VCC-1V8: C224.2 R295.1 R296.1 R297.1 R298.1 RA103.1 U5.2 | length 8262.5
  Top w10: R295.1@1537.49,328.31 v1(1561.11,328.31) ; v1(1620.17,328.31) R296.1@1643.79,328.31 ; v1(1718.59,328.31) R297.1@1742.21,328.31 ; v1(1789.24,327.1) 1831.85,327.1 1898.33,260.62 2299.49,260.62 v1(2343.12,304.25) ; U5.2@2648.46,3238.96 2648.46,3137.91 2663.41,3122.95 2702.42,3122.95 2786.11,3122.95 2795.46,3113.6 2795.46,2907.93 2931.04,2772.35 v1(2931.04,2753.28) ; v1(2926.06,2589.63) 2920.05,2583.62 2640.15,2583.62 2507.18,2450.65 2507.18,1885.47 2384.94,1763.23 v1(2384.94,524.09) 2391.03,518 3294.56,518 v1(3303.66,527.1) ; v1(3461.32,330.24) 3473.12,330.24 3636.1,167.26 3760.49,42.84 3760.49,-163.28 3840.5,-243.29 4370.23,-243.29 4403.67,-209.85 4980.61,-209.85 5003.41,-187.05 5003.41,77.23 R298.1@5188.98,262.8
  Top w30: RA103.1@2544.29,3279.53 2665.29,3279.53 C224.2@2665.29,3278.7 2648.46,3278.7 U5.2@2648.46,3238.96
  Bottom w10: v1(1561.11,328.31) v1(1620.17,328.31) v1(1718.59,328.31) ; v1@1718.59,324.7 v1(1718.59,328.31) ; v1(1789.24,327.1) 1789.24,328.31 v1(1718.59,328.31) ; v1(2343.12,304.25) 2382.61,343.74 2382.61,524.09 v1(2384.94,524.09) ; v1(2926.06,2589.63) 2935.4,2598.97 2935.4,2745.47 2929.31,2751.56 v1(2931.04,2753.28) ; v1(3303.66,527.1) 3303.66,482.25 3458.5,327.41 v1(3461.32,330.24)
VCC-3V3: C2.1 C4.2 C5.1 C7.1 C37.1 D86.1 D90.1 D93.2 D129.2 FB2.1 J4.4 J7.1 J10.2 J22.1 J30.7 J38.1 J39.2 J39.3 J41.4 L5.2 Q1.1 Q3.2 Q8.2 R7.2 R10.1 R11.1 R27.2 R44.2 R206.1 R213.2 R214.2 R267.1 R290.1 R291.2 RA27.2 RA28.2 RA29.1 RA102.1 | length 22362.1
  Top w6: R44.2@3867.13,594.49 3905.51,594.49 3951.35,640.33 v1(3970.65,640.33)
  Top w10: RA102.1@2106.3,3333.66 2050.33,3333.66 2025.14,3308.48 2025.14,2900.16 2049.07,2876.23 2254.08,2876.23 2268.31,2890.46 2268.31,2912.23 ; RA29.1@2279.53,2936.02 2268.31,2924.81 2268.31,2912.55 2268.31,2912.23 ; RA28.2@2413.39,2936.02 RA28.2@2413.39,2936.02 2413.33,2905.93 v1(2422.63,2896.6) ; RA27.2@2464.57,2936.02 2494.99,2905.6 v1(2494.99,2898.37) ; v1(2602.77,3245.65) 2602.77,3230.92 2622.29,3211.4 2622.29,3062.55 2715.3,2969.54 2715.3,2920.68 v1(2693.49,2898.87) ; R267.1@3095.47,2874.02 C7.1@3095.47,2834.65 3307.09,2834.65 3330.24,2857.8 3330.24,3199.15 ; C2.1@3248.03,3216.93 3329.66,3216.93 3338.84,3207.75 3330.24,3199.15 ; C5.1@3303.15,3205.71 3322.84,3205.71 ; R11.1@3529.64,3169.36 3527.56,3169.36 3527.56,3146.01 v1(3529.72,3146.01) ; 3854.77,3083.41 3859.63,3088.27 3859.64,3087.13 ; 3859.12,3087.9 3860.66,3089.44 3860.8,3089.44 ; R10.1@3883.97,3169.36 3887.08,3169.36 3903.15,3153.29 ; 3915.45,3144.09 3912.35,3144.09 3910.75,3145.69 ; 4582.9,627.06 4593.09,637.25 ; 4592.62,644.86 4593.64,643.84 ; R27.2@4699.8,637.8 4599.68,637.8 ; v1(4975.1,1425.85) 4987.5,1438.25 R214.2@5001.75,1438.25 ; v1(4976.42,1493.35) R7.2@5001.75,1493.37 ; v1(4982.11,1355.95) 4982.11,1374.45 4986.85,1379.2 R213.2@5001.75,1379.2 ; v1(4996.93,2617.9) 5006.58,2627.54 5055.22,2627.54 5073.35,2645.67 R290.1@5106.3,2645.67 R206.1@5106.3,2606.3 ; 2268.31,2912.23 2268.12,2912.23 v1(2268.12,2900.02) 2268.31,2912.23 ; 3322.84,3205.71 3329.4,3199.15 3330.24,3199.15 ; 3322.84,3205.71 3330.24,3205.71 3330.24,3199.15 ; 3903.15,3153.29 3903.15,3140.5 3909.54,3146.89 ; 3903.15,3153.29 3909.54,3146.89 ; 3903.15,3153.29 3918.36,3153.29 3910.75,3145.69 ; 3909.54,3146.89 3910.75,3145.69 ; 4593.09,637.25 4593.09,638.09 4593.64,638.64 ; 4593.09,637.25 4593.09,631.21 4599.68,637.8 ; 4593.09,637.25 4593.64,637.8 ; 4593.64,637.8 4593.64,638.64 ; 4593.64,637.8 4599.68,637.8 ; 4593.64,638.64 4593.64,643.84 ; 4593.64,643.84 4599.68,637.8
  Top w12: Q8.2@834.28,2135.93 834.28,2140.67 1051.15,2140.67 v1(1052.53,2139.28) ; v1(1052.2,1932.75) 1077.76,1932.75 R291.2@1077.76,1933.07 ; Q3.2@3887.89,413.76 3916.02,413.76 3956.8,454.54 4094.45,454.54 4122.75,482.84 v1(4122.75,640.54) ; J10.2@5224.41,1507.87 5266.12,1507.87 5272.37,1514.12 ; J39.3@5228.35,2555.12 5191.13,2555.12 5186.22,2560.03 5186.22,2569.23 5191.96,2574.97 5228.35,2574.97 J39.2@5228.35,2574.8 5274.9,2574.8
  Top w15: J7.1@-169.29,2003.94 -125.64,2003.94 7.46,1870.84 218.78,1870.84 263.78,1825.84 D93.2@263.78,1799.84 270.28,1799.84 307.59,1762.53 386.81,1762.53 395.78,1771.5 526.67,1771.5 546.53,1791.36 546.53,1906.6 v1(576.53,1936.6) ; v1(576.52,2536.57) 576.52,2862.34 v1(576.93,2862.34)
  Top w20: J30.7@780.31,3688.98 844.85,3688.98 854.33,3679.49 854.33,3663.92 ; D90.1@854.33,3549.5 854.33,3631.8 ; v1(1188.98,3645.67) 1187.23,3647.42 872.02,3647.42 ; v1(1590.34,3647.85) 1590.34,3727.6 1644.75,3782.01 v1(2206.25,3782.01) ; v1(3970.65,640.33) 3970.65,640.75 C37.1@4000,640.75 ; 4582.9,478.05 4600.62,495.77 ; 4582.9,495.77 4600.62,495.77 ; 4582.9,515.77 4584.18,515.77 4604.18,495.77 ; Q1.1@4822.46,517.62 4800.62,495.77 4604.18,495.77 ; 854.33,3631.8 854.33,3647.42 ; 854.33,3631.8 869.95,3647.42 ; 854.33,3647.42 854.33,3663.92 ; 854.33,3647.42 869.95,3647.42 ; 854.33,3663.92 855.51,3663.92 872.02,3647.42 ; 869.95,3647.42 872.02,3647.42 ; 4600.62,495.77 4604.18,495.77
  Top w30: 3578.84,3410.95 3612.21,3377.58 ; 3613.22,3410.95 3612.21,3409.94 3612.21,3377.58 ; 3646.84,3410.95 3612.21,3376.32 ; C4.2@3669.29,3197.24 3662.45,3204.09 D129.2@3616.26,3204.09 3612.21,3204.09 J4.4@3612.21,3285.43 3612.21,3376.32 ; FB2.1@3851.39,2941.94 3851.39,3080.17 3859.12,3087.9 ; 3859.64,3088.28 3860.8,3089.44 3915.45,3144.09 3964.07,3192.71 3964.07,3310.05 ; 3964.07,3340.82 3964.07,3310.05 ; 3994.84,3340.82 3964.07,3310.05 ; v1(4180.85,637.17) 4287.54,743.86 4615.5,743.86 4625.98,733.38 D86.1@4625.98,702.86 4582.9,659.77 4582.9,627.06 4582.9,515.77 4582.9,495.77 4582.9,478.05 4582.9,202.71 ; 4560.84,175.57 4560.84,180.65 4582.9,202.71 ; 4582.9,175.57 4582.9,199.09 ; 4608.15,175.57 4584.63,199.09 4582.9,199.09 ; 5272.37,1514.12 5294.17,1514.12 5307.71,1500.58 v1(5307.71,1467.5) ; 5274.9,2574.8 5339.43,2574.8 5355.96,2558.27 v1(5355.96,2482.21) ; 5419.54,556 5429.17,556 ; 3612.21,3376.32 3612.21,3377.58 ; 4582.9,199.09 4582.9,202.71
  Top w40: v1(4206.78,83.23) v1(4226.78,103.23) 4299.12,175.57 4560.84,175.57 4582.9,175.57 4608.15,175.57 5027.27,175.57 5148.36,296.66 5148.36,427.97 5192.29,471.9 5367.71,471.9
  Top w59.06: C2.1@3259.94,3228.84 3359.6,3228.84 3407.23,3276.47 3407.23,3368.95 v1@3444,3405.72 ; v1(3444,3404) v1@3444,3405.72 ; v1(4646.84,2963.15) v1(4646.84,2999.15) 4646.84,3251.53 4530.12,3368.25 4083.07,3368.25 4055.64,3340.82 3994.84,3340.82 3964.07,3340.82 3893.94,3410.95 3646.84,3410.95 3613.22,3410.95 3578.84,3410.95 3449.23,3410.95 v1@3444,3405.72 ; v1(5267.76,1245.88) v1(5247.76,1225.88) 5207.97,1186.09 5207.97,895.18 5429.17,673.98 5429.17,556 5429.17,533.36 5367.71,471.9 ; v1(5297.32,2129.67) v1(5325.32,2157.67) 5355.96,2188.31 v1(5355.96,2450.21) v1(5355.96,2482.21)
  Bottom w10: v1(2268.12,2900.02) 2268.12,2900.54 2494.99,2900.54 v1(2494.99,2898.37) ; v1@2494.99,2898.16 v1(2494.99,2898.37) ; v1(2602.77,3245.65) 2602.77,3357.92 2660.13,3415.28 2685.13,3415.28 ; v1@2693.49,2898.16 v1(2693.49,2898.87) 2688.64,2894.02 2499.34,2894.02 v1(2494.99,2898.37) ; 2695.04,3415.28 2685.13,3415.28 ; 2695.04,3425.19 2685.13,3415.28 ; v1(3444,3404) 3505.72,3404 3529.72,3380 v1(3529.72,3146.01) ; 3857.12,3084.43 3857.12,3084.61 ; v1(4982.11,1355.95) 4976.42,1361.65 v1(4976.42,1493.35) 4976.42,1526.93 4998.81,1549.32 5266.02,1549.32 ; v1(4996.93,2617.9) 4996.93,2705.28 ; 5000.09,2738.24 4996.93,2735.08 4996.93,2722.24 ; 5300.32,1508.26 5309.66,1517.6 5297.67,1529.59 5277.94,1549.32 ; 4996.93,2705.28 4996.93,2722.24 ; 4996.93,2705.28 5007.19,2715.54 5000.49,2722.24 4996.93,2722.24 ; 5266.02,1549.32 5273.16,1542.18 5277.94,1546.97 5277.94,1549.32 ; 5266.02,1549.32 5274.44,1557.73 5277.94,1554.23 5277.94,1549.32 ; 5266.02,1549.32 5277.94,1549.32
  Bottom w12: 576.48,2129.02 577.55,2129.02 587.81,2139.28 ; 576.48,2148.17 578.92,2148.17 587.81,2139.28 ; v1(1052.2,1932.75) 1052.53,1933.08 1052.53,2122.89 ; 587.81,2139.28 1036.14,2139.28 ; 1036.14,2139.28 1052.53,2122.89 ; 1036.14,2139.28 v1(1052.53,2139.28) 1052.53,2122.89
  Bottom w15: v1@576.48,2536.53 576.48,2148.17 576.48,2129.02 576.48,2008.78 576.53,2008.74 v1(576.53,1936.6) ; v1(576.93,2830.34) v1(576.93,2862.34) 576.93,3485.59 J30.7@780.31,3688.98
  Bottom w20: v1(1188.98,3645.67) 1590.34,3645.67 v1(1590.34,3647.85) ; v1(2206.25,3782.01) 2646.9,3782.01 2695.04,3733.86 2695.04,3425.19 2695.04,3415.28 2705.21,3405.12 J38.1@2748.03,3405.12 ; v1(3970.65,640.33) 4122.75,640.33 v1(4122.75,640.54) 4182.68,640.54 4182.78,640.44 v1(4180.85,637.17)
  Bottom w30: J38.1@2748.03,3405.12 J22.1@3059.06,3405.12 3442.88,3405.12 v1(3444,3404)
  Bottom w40: J41.4@3661.42,82.68 4205.72,82.68 4205.72,83.23 v1(4206.78,83.23) v1(4226.78,103.23)
  Bottom w59.06: v1(5247.76,1225.88) v1(5267.76,1245.88) 5297.67,1275.79 5297.67,1529.59 5297.67,1682.56 5297.32,1682.91 v1(5297.32,2129.67) v1@5321.32,2153.67
  Bottom w61.42: v1(5355.96,2450.21) v1(5355.96,2482.21) 5415.53,2541.78 5415.53,2611.66 5288.95,2738.24 5000.09,2738.24 4775.18,2963.15 4690.84,2963.15 ; 4690.84,2963.15 v1(4646.84,2963.15) v1(4646.84,2999.15) 4654.84,2999.15 4690.84,2963.15
VCC_4G: C71.1 C73.1 C75.1 C192.1 CON2.2 CON2.24 CON2.39 CON2.41 CON2.52 D53.1 L2.2 R100.2 R173.1 | length 2557.1
  Top w6: 861.91,685.83 866.85,680.89 871.79,685.83 903.4,717.43 909.45,717.43 914.4,717.43 909.45,722.38
  Top w10: v1(738.89,272.13) 738.89,248.03 C192.1@739.17,248.03 R173.1@739.17,208.66 ; 1164.16,343.37 1164.16,351.87 ; CON2.52@1350.4,777.62 1350.4,830.51 1356.28,836.39 1544.06,836.39 1580.24,800.21 D53.1@1580.24,799.21
  Top w25: CON2.2@437.01,777.62 437.01,720.47 443.39,703.66 ; R100.2@898.62,854.33 909.45,843.5 CON2.24@909.45,777.62 909.45,722.38 ; 906.37,685.83 909.45,688.92 909.45,717.43 909.45,722.38 ; 946.96,685.83 910.41,722.38 909.45,722.38 ; 1344.07,705.43 1344.07,718.09 1350.4,724.41 CON2.52@1350.4,777.62
  Top w50: 443.39,703.66 461.22,685.83 861.91,685.83 871.79,685.83 906.37,685.83 946.96,685.83 1127.38,685.83 ; 1164.16,351.87 1164.16,647.35 1165.01,648.2 ; 1344.07,705.43 1324.48,685.83 1202.64,685.83 ; 1127.38,685.83 1202.64,685.83 ; 1127.38,685.83 1165.01,648.2 ; 1165.01,648.2 1202.64,685.83
  Bottom w10: v1(738.89,272.13) 1149.58,272.13 v1(1149.58,272.28)
VCOM: J39.1 R199.2 R289.1 | length 297.1
  Top w6: R199.2@5139.76,2811.02 R289.1@5139.76,2771.65 5179.16,2771.65 5188.66,2762.15 5188.66,2598.64 5192.82,2594.49 J39.1@5228.35,2594.49
VDD-CORE/HP-DET: CA11.1 RA12.1 UA1.35 | length 137.9
  Top w8: UA1.35@2422.44,3136.84 2457.67,3136.84
  Top w10: 2457.67,3136.84 2463.69,3136.84 2482.17,3118.36 RA12.1@2510.18,3118.36 ; RA12.1@2510.83,3118.11 2510.18,3118.11 RA12.1@2510.18,3118.36 ; CA11.1@2510.83,3157.48 2508.89,3157.48 2509.86,3156.51 2510.18,3156.19 RA12.1@2510.18,3118.36
VGH: C60.1 C233.1 D82.2 J39.38 R59.2 R60.2 | length 1234.3
  Top w12: J39.38@5228.35,1866.14 5272.85,1866.14
  Top w20: C60.1@5236.22,2779.53 5236.22,2751.5 5260.57,2727.15 5414.06,2727.15 5432.01,2709.2 5432.01,2142.3 v1(5394.15,2104.44) ; 5272.85,1866.14 5344.81,1866.14 5394.18,1915.51 v1(5394.18,2003.4)
  Bottom w20: v1(5394.18,2003.4) v1@5394.18,2101.77
VGL: C55.1 C58.1 D84.1 J39.35 R61.2 R62.2 | length 1297
  Top w12: J39.35@5228.35,1925.2 5272.57,1925.2
  Top w20: C58.1@4956.69,2692.91 4956.69,2672.9 4969.05,2660.54 5038.71,2660.54 v1(5056.06,2677.89) ; 5272.57,1925.2 5340.4,1925.2 5356.71,1941.51 v1(5356.71,2001.19) ; v1(5356.9,2117.44) 5401.49,2162.03 5401.49,2558.16 v1(5367.63,2592.01)
  Bottom w20: v1(5056.06,2677.89) 5281.75,2677.89 v1(5367.63,2592.01) ; v1(5356.71,2001.19) 5356.71,2117.25 v1(5356.9,2117.44)
VPP/VCC: CA10.1 RA9.2 RA10.1 UA1.15 | length 197.4
  Top w8: 2189.3,3152.69 2192.52,3152.58 UA1.15@2221.65,3152.58
  Top w10: RA9.2@2123.03,3086.61 2118.72,3086.24 2118.72,3086.61 2118.72,3159.8 CA10.1@2123.03,3161.42 2138.32,3176.7 2164.91,3176.7 2188.92,3152.69 2189.3,3152.69
VRA1/MIC2P: CA2.1 UA1.14 | length 116
  Top w6: CA2.1@2123.03,3204.72 2123.03,3200.84 2160.57,3200.84 2193.08,3168.33 UA1.14@2221.65,3168.33
VRA2/MIC2N: CA4.2 RA6.2 UA1.13 | length 175.2
  Top w6: CA4.2@2123.03,3287.4 2123.03,3250.03 2117.1,3244.09 RA6.2@2123.03,3244.09 2152.97,3214.16 2164.22,3214.16 2194.3,3184.08 UA1.13@2221.65,3184.08
VRN/AGND: RA26.1 UA1.6 | length 113.4
  Top w8: UA1.6@2314.17,3245.1 2314.17,3274.37
  Top w10: RA26.1@2263.78,3333.66 2263.78,3329.07 2270.55,3329.07 2313.92,3285.71 2313.92,3274.84 2314.17,3274.59 2314.17,3274.37
VRP/AVCC: CA1.2 UA1.5 | length 108
  Top w8: UA1.5@2329.92,3245.1 2329.92,3277.64
  Top w10: CA1.2@2314.96,3338.19 2304.43,3327.66 2304.43,3317.9 2329.92,3292.41 2329.92,3277.64
W_DISABLE_N: CON2.20 R100.1 | length 84.5
  Top w6: CON2.20@846.46,777.62 846.46,835.63 R100.1@865.16,854.33
XTAL-25MIN: CE18.2 U15.36 X1.3 | length 328.6
  Top w8: U15.36@4226.38,2696.85 4283.62,2696.85 4295.6,2708.83 4382.71,2708.83 CE18.2@4393.7,2697.83 4420.94,2725.07 4477.24,2725.07 4503.24,2699.08 X1.3@4517.72,2685.04
XTAL-25MOUT: CE17.2 R109.2 U15.37 X1.1 | length 266.9
  Top w8: U15.37@4226.38,2712.6 4279.57,2712.6 4289.82,2722.85 4341.05,2722.85 4347.85,2729.65 4347.85,2750.06 R109.2@4351.38,2759.84 4386.81,2759.84 CE17.2@4393.7,2766.73 4437.99,2766.73 X1.1@4450.79,2779.53
pads on no net: CON2.1 CON2.3 CON2.5 CON2.6 CON2.7 CON2.11 CON2.13 CON2.16 CON2.17 CON2.19 CON2.22 CON2.23 CON2.25 CON2.28 CON2.30 CON2.31 CON2.32 CON2.33 CON2.44 CON2.45 CON2.46 CON2.47 CON2.48 CON2.49 CON2.50 CON2.51 CON2._/2 CON2._/3 CON2.G1 CON2.G2 FID1.1 FID2.1 FID3.1 FID5.1 H1.1 H2.1 H3.1 H4.1 H6.1 H7.1 J2.1 J2.4 J2.5 J4._ J4._/2 J5.15 J5.16 J5.17 J5.18 J8.4 J8.6 J8.12 J8.13 J10.7 J10.8 J16.5 J16.6 J36.1 J36.6 J36.7 J39.4 J39.23 J39.24 J39.26 J39.27 J39.36 J39.37 J39.41 J39.42 U10.3 U10.4 U10.13 U10.14 U11.4 U11.5 U11.6 U15.34 U17.14 U64.1 U64.2 U64.3 U64.4 U64.5 U64.130 U64.131 U64.132 U64.134 U64.151 U64.152 U64.153 U64.154 U64.159 U64.160 U64.161 U64.174 U64.184 U64.185 U64.186 U64.187 USB4.5 USB4.6 USB4.8 USB4.9 X3.2 X3.4
copper on no net: | length 0.1

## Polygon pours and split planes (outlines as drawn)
GND on Bottom (solid, remove dead copper, pour order 0): -919.5,4388.12 -919.5,-773.4 6023.87,-773.4 6023.87,4388.12
GND on Top (solid, remove dead copper, pour order 2): -668.53,4296.1 -668.53,-555.89 5764.54,-555.89 5764.54,4296.1

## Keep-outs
Top:
  region: 4120.7,1913.77 4120.7,1885.77 4122.7,1885.77 4122.7,1913.77 4120.7,1913.77
  region: 3470,3122 3470,3120 3496,3120 3496,3122 3470,3122
  region: 4343.17,2511.91 4343.17,2432.51 4453.9,2432.51 4453.9,2511.91 4343.17,2511.91
  region: 322,2590 322,2570 324,2570 324,2590 322,2590
  region: 4984,2364 4984,2336 4986,2336 4986,2364 4984,2364
  region: 900.4,-7.3 900.4,-60.4 1054.61,-60.4 1054.61,-7.3 900.4,-7.3
  region: 3984.89,2985.25 3984.89,2983.25 4006.89,2983.25 4006.89,2985.25 3984.89,2985.25
  region: 4856.89,831.25 4856.89,811.25 4858.89,811.25 4858.89,831.25 4856.89,831.25
  region: 4972,2488 4972,2458 4974,2458 4974,2488 4972,2488
  region: 4800.49,3287.68 4800.49,3145.53 4984.44,3145.53 4984.44,3287.68 4800.49,3287.68
  region: 3706,1442 3706,1440 3744,1440 3744,1442 3706,1442
  region: 3632.89,1211.25 3632.89,1185.25 3634.89,1185.25 3634.89,1211.25 3632.89,1211.25
  region: 3730.7,1379.77 3730.7,1359.77 3732.7,1359.77 3732.7,1379.77 3730.7,1379.77
  region: -281.11,2303.25 -281.11,2301.25 -261.11,2301.25 -261.11,2303.25 -281.11,2303.25
  region: 3582.89,1095.25 3582.89,1057.25 3584.89,1057.25 3584.89,1095.25 3582.89,1095.25
  region: 1566,3578 1566,3576 1596,3576 1596,3578 1566,3578
  region: 2700.89,191.25 2700.89,189.25 2724.89,189.25 2724.89,191.25 2700.89,191.25
  region: 4426.76,2808.73 4426.76,2653.97 4544.21,2653.97 4544.21,2808.73 4426.76,2808.73
  region: 4778.89,3137.25 4778.89,3135.25 4802.89,3135.25 4802.89,3137.25 4778.89,3137.25
  region: 3498,3104 3498,3100 3530,3100 3530,3104 3498,3104
  region: 3036.89,-96.75 3036.89,-98.75 3052.89,-98.75 3052.89,-96.75 3036.89,-96.75
  region: 3776,470 3776,468 3798,468 3798,470 3776,470
  region: 3043.72,3256.48 3043.72,3069.41 3196.17,3069.41 3196.17,3256.48 3043.72,3256.48
  region: 4264.65,1270.24 4264.65,1139.09 4438.4,1139.09 4438.4,1270.24 4264.65,1270.24
  region: 510.37,-6.75 510.37,-64.21 664.79,-64.21 664.79,-6.75 510.37,-6.75
  region: 3696.89,1119.25 3696.89,1095.25 3698.89,1095.25 3698.89,1119.25 3696.89,1119.25
  region: 296,2536 296,2534 326,2534 326,2536 296,2536
  region: 4887,364.07 ccw(c4784.64,364.07) 4784.64,466.43 ccw(c4784.64,364.07) 4682.28,364.07 ccw(c4784.64,364.07) 4784.64,261.7 ccw(c4784.64,364.07)
  region: 276.89,2143.25 276.89,2119.25 278.89,2119.25 278.89,2143.25 276.89,2143.25
  region: 654,464 654,462 674,462 674,464 654,464
Bottom:
  region: 34.89,2367.25 34.89,2365.25 78.89,2365.25 78.89,2367.25 34.89,2367.25
Keep-Out Layer:
  lines w10: 796.45,2745.96 938.18,2745.96 ; 2820.92,642.49 2939.03,642.49 ; 2820.92,2434.39 2939.03,2434.39 ; 4713.77,364.07 4855.51,364.07 ; -390.17,-157.48 ccw(c-272.06,-157.48) -272.06,-275.59 5397.23,-275.59 ccw(c5397.23,-157.48) 5515.34,-157.48 5515.34,3740.16 ccw(c5397.23,3740.16) 5397.23,3858.27 -272.06,3858.27 ccw(c-272.06,3740.16) -390.17,3740.16 -390.17,-157.48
